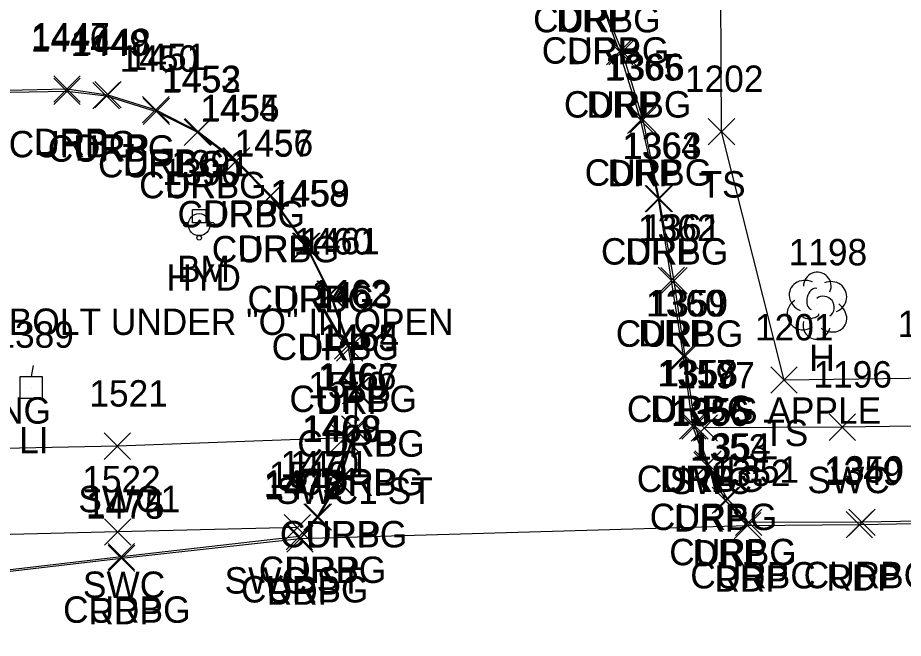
# Model space of a CAD drawing. Extents: x 1715662 to 1717487, y 887396 to 890004.
# Drawn here: x 1716283.7 to 1716350.8, y 888258 to 888305 of the extents above; entities that cross this region are included whole.
import ezdxf

# ---------------------------------------------------------------- set-up
doc = ezdxf.new("R2010")
doc.units = 0
for name, color, linetype in [('C_A', 7, 'Continuous'), ('C_C', 7, 'Continuous'), ('C_I', 7, 'Continuous'), ('CPBM', 7, 'Continuous'), ('L_A', 7, 'Continuous'), ('L_C', 7, 'Continuous'), ('L_I', 7, 'Continuous'), ('L_TIC', 7, 'Continuous'), ('LELB', 7, 'Continuous'), ('LTD', 7, 'Continuous'), ('P_A', 7, 'Continuous'), ('P_I', 7, 'Continuous'), ('P_TIC', 7, 'Continuous'), ('PET', 7, 'Continuous'), ('R_A', 7, 'Continuous'), ('R_I', 7, 'Continuous'), ('R_TIC', 7, 'Continuous'), ('RC', 7, 'Continuous'), ('RDP', 7, 'Continuous'), ('RSW', 7, 'Continuous'), ('S_C', 7, 'Continuous'), ('U_A', 7, 'Continuous'), ('U_I', 7, 'Continuous'), ('ULP', 7, 'Continuous'), ('UWFH', 7, 'Continuous')]:
    doc.layers.add(name, color=color, linetype=linetype)

msp = doc.modelspace()

# ---------------------------------------------------------------- linework, layer by layer
at = {"layer": 'CPBM'}
for p, q in [((1716296.998, 888289.479), (1716296.998, 888290.479)), ((1716296.998, 888290.479), (1716297.998, 888290.479)), ((1716297.5, 888289.979), (1716297.5, 888289.979)), ((1716297.5, 888289.979), (1716297.5, 888289.979)), ((1716297.998, 888290.479), (1716297.998, 888289.479)), ((1716297.998, 888289.479), (1716296.998, 888289.479))]:
    msp.add_line(p, q, dxfattribs=at)
at = {"layer": 'L_TIC'}
for points in [[(1716336.074, 888295.382), (1716338.074, 888297.382)], [(1716338.074, 888295.382), (1716336.074, 888297.382)], [(1716340.818, 888276.563), (1716342.818, 888278.563)], [(1716342.818, 888276.563), (1716340.818, 888278.563)]]:
    msp.add_lwpolyline(points, dxfattribs=at)
at = {"layer": 'LELB'}
msp.add_lwpolyline([(1716373.854, 888277.981), (1716341.818, 888277.563), (1716337.074, 888296.382), (1716336.988, 888312.112), (1716344.519, 888320.79), (1716334.379, 888337.453)], dxfattribs=at)
at = {"layer": 'LTD'}
msp.add_line((1716344.289, 888283.248), (1716344.289, 888283.248), dxfattribs=at)
msp.add_line((1716344.289, 888283.248), (1716344.289, 888283.248), dxfattribs=at)
msp.add_arc((1716344.336, 888284.682), 1.047, 335.52715, 180.95627, dxfattribs=at)
for centre, major_axis, ratio, start_param, end_param in [((1716343.498, 888283.914), (1.21, -0.512), 0.895232, 1.570796, 4.712389), ((1716345.331, 888283.831), (-1.141, -0.483), 0.949671, 1.570796, 4.712389), ((1716344.081, 888283.706), (-0.208, -0.792), 0.645439, 3.141593, 6.283185), ((1716344.789, 888283.081), (-0.5, 0.667), 0.989748, 3.141593, 6.283185), ((1716343.206, 888282.539), (0.584, -1.042), 0.959034, 3.141593, 6.283185), ((1716345.289, 888282.414), (-1.09, 0.792), 0.841452, 1.570796, 4.712389), ((1716344.29, 888281.748), (0.265, 1.061), 0.942809, 1.570796, 4.712389), ((1716343.831, 888282.498), (-0.625, -0.083), 0.423636, 0, 3.141593)]:
    msp.add_ellipse(centre, major_axis=major_axis, ratio=ratio, start_param=start_param, end_param=end_param, dxfattribs=at)
at = {"layer": 'P_TIC'}
for points in [[(1716338.044, 888265.533), (1716340.044, 888267.533)], [(1716340.044, 888265.533), (1716338.044, 888267.533)], [(1716346.525, 888265.611), (1716348.525, 888267.611)], [(1716348.525, 888265.611), (1716346.525, 888267.611)], [(1716304.127, 888264.54), (1716306.127, 888266.54)], [(1716306.127, 888264.54), (1716304.127, 888266.54)], [(1716290.61, 888263.06), (1716292.61, 888265.06)], [(1716292.61, 888263.06), (1716290.61, 888265.06)]]:
    msp.add_lwpolyline(points, dxfattribs=at)
at = {"layer": 'PET'}
msp.add_lwpolyline([(1716527, 888260.728), (1716516.575, 888259.254), (1716502.433, 888259.092), (1716473.824, 888260.93), (1716440.241, 888263.084), (1716411.867, 888267.674), (1716401.494, 888267.443), (1716378.307, 888267.153), (1716347.525, 888266.611), (1716339.044, 888266.533), (1716305.127, 888265.54), (1716291.61, 888264.06), (1716269.77, 888261.49)], dxfattribs=at)
at = {"layer": 'R_TIC'}
for points in [[(1716328.357, 888301.427), (1716330.357, 888303.427)], [(1716330.357, 888301.427), (1716328.357, 888303.427)], [(1716328.548, 888301.44), (1716330.548, 888303.44)], [(1716330.548, 888301.44), (1716328.548, 888303.44)], [(1716286.478, 888298.606), (1716288.478, 888300.606)], [(1716288.478, 888298.606), (1716286.478, 888300.606)], [(1716286.483, 888298.431), (1716288.483, 888300.431)], [(1716288.483, 888298.431), (1716286.483, 888300.431)], [(1716289.447, 888298.096), (1716291.447, 888300.096)], [(1716291.447, 888298.096), (1716289.447, 888300.096)], [(1716289.586, 888298.167), (1716291.586, 888300.167)], [(1716291.586, 888298.167), (1716289.586, 888300.167)], [(1716293.21, 888297.032), (1716295.21, 888299.032)], [(1716295.21, 888297.032), (1716293.21, 888299.032)], [(1716293.246, 888296.912), (1716295.246, 888298.912)], [(1716295.246, 888296.912), (1716293.246, 888298.912)], [(1716329.95, 888296.244), (1716331.95, 888298.244)], [(1716331.95, 888296.244), (1716329.95, 888298.244)], [(1716330.126, 888296.278), (1716332.126, 888298.278)], [(1716332.126, 888296.278), (1716330.126, 888298.278)], [(1716296.419, 888295.376), (1716298.419, 888297.376)], [(1716298.419, 888295.376), (1716296.419, 888297.376)], [(1716296.366, 888295.331), (1716298.366, 888297.331)], [(1716298.366, 888295.331), (1716296.366, 888297.331)], [(1716299.274, 888293.125), (1716301.274, 888295.125)], [(1716301.274, 888293.125), (1716299.274, 888295.125)], [(1716299.338, 888293.175), (1716301.338, 888295.175)], [(1716301.338, 888293.175), (1716299.338, 888295.175)], [(1716301.866, 888290.476), (1716303.866, 888292.476)], [(1716303.866, 888290.476), (1716301.866, 888292.476)], [(1716301.933, 888290.519), (1716303.933, 888292.519)], [(1716303.933, 888290.519), (1716301.933, 888292.519)], [(1716331.288, 888290.299), (1716333.288, 888292.299)], [(1716333.288, 888290.299), (1716331.288, 888292.299)], [(1716331.357, 888290.306), (1716333.357, 888292.306)], [(1716333.357, 888290.306), (1716331.357, 888292.306)], [(1716304.575, 888286.699), (1716306.575, 888288.699)], [(1716306.575, 888286.699), (1716304.575, 888288.699)], [(1716304.656, 888286.714), (1716306.656, 888288.714)], [(1716306.656, 888286.714), (1716304.656, 888288.714)], [(1716332.274, 888284.104), (1716334.274, 888286.104)], [(1716334.274, 888284.104), (1716332.274, 888286.104)], [(1716332.482, 888284.082), (1716334.482, 888286.082)], [(1716334.482, 888284.082), (1716332.482, 888286.082)], [(1716306.406, 888283.086), (1716308.406, 888285.086)], [(1716308.406, 888283.086), (1716306.406, 888285.086)], [(1716306.48, 888283.067), (1716308.48, 888285.067)], [(1716308.48, 888283.067), (1716306.48, 888285.067)], [(1716307.753, 888279.143), (1716309.753, 888281.143)], [(1716309.753, 888279.143), (1716307.753, 888281.143)], [(1716307.904, 888278.993), (1716309.904, 888280.993)], [(1716309.904, 888278.993), (1716307.904, 888280.993)], [(1716333.186, 888278.376), (1716335.186, 888280.376)], [(1716335.186, 888278.376), (1716333.186, 888280.376)], [(1716333.322, 888278.378), (1716335.322, 888280.378)], [(1716335.322, 888278.378), (1716333.322, 888280.378)], [(1716308.35, 888275.756), (1716310.35, 888277.756)], [(1716310.35, 888275.756), (1716308.35, 888277.756)], [(1716308.436, 888275.784), (1716310.436, 888277.784)], [(1716310.436, 888275.784), (1716308.436, 888277.784)], [(1716308.29, 888272.841), (1716310.29, 888274.841)], [(1716310.29, 888272.841), (1716308.29, 888274.841)], [(1716308.376, 888272.785), (1716310.376, 888274.785)], [(1716310.376, 888272.785), (1716308.376, 888274.785)], [(1716333.899, 888273.075), (1716335.899, 888275.075)], [(1716335.899, 888273.075), (1716333.899, 888275.075)], [(1716334.071, 888273.086), (1716336.071, 888275.086)], [(1716336.071, 888273.086), (1716334.071, 888275.086)], [(1716334.781, 888272.932), (1716336.781, 888274.932)], [(1716336.781, 888272.932), (1716334.781, 888274.932)], [(1716345.221, 888272.995), (1716347.221, 888274.995)], [(1716347.221, 888272.995), (1716345.221, 888274.995)], [(1716307.53, 888272.184), (1716309.53, 888274.184)], [(1716309.53, 888272.184), (1716307.53, 888274.184)], [(1716290.3, 888271.553), (1716292.3, 888273.553)], [(1716292.3, 888271.553), (1716290.3, 888273.553)], [(1716334.981, 888270.089), (1716336.981, 888272.089)], [(1716336.981, 888270.089), (1716334.981, 888272.089)], [(1716335.051, 888270.2), (1716337.051, 888272.2)], [(1716337.051, 888270.2), (1716335.051, 888272.2)], [(1716307.028, 888268.889), (1716309.028, 888270.889)], [(1716309.028, 888268.889), (1716307.028, 888270.889)], [(1716307.107, 888268.878), (1716309.107, 888270.878)], [(1716309.107, 888268.878), (1716307.107, 888270.878)], [(1716336.372, 888267.457), (1716338.372, 888269.457)], [(1716338.372, 888267.457), (1716336.372, 888269.457)], [(1716336.533, 888267.537), (1716338.533, 888269.537)], [(1716338.533, 888267.537), (1716336.533, 888269.537)], [(1716336.533, 888267.537), (1716338.533, 888269.537)], [(1716338.533, 888267.537), (1716336.533, 888269.537)], [(1716305.434, 888266.196), (1716307.434, 888268.196)], [(1716307.434, 888266.196), (1716305.434, 888268.196)], [(1716305.525, 888266.198), (1716307.525, 888268.198)], [(1716307.525, 888266.198), (1716305.525, 888268.198)], [(1716303.924, 888265.392), (1716305.924, 888267.392)], [(1716305.924, 888265.392), (1716303.924, 888267.392)], [(1716338.044, 888265.533), (1716340.044, 888267.533)], [(1716340.044, 888265.533), (1716338.044, 888267.533)], [(1716338.127, 888265.78), (1716340.127, 888267.78)], [(1716340.127, 888265.78), (1716338.127, 888267.78)], [(1716346.715, 888265.797), (1716348.715, 888267.797)], [(1716348.715, 888265.797), (1716346.715, 888267.797)], [(1716290.325, 888265.062), (1716292.325, 888267.062)], [(1716292.325, 888265.062), (1716290.325, 888267.062)], [(1716304.079, 888264.717), (1716306.079, 888266.717)], [(1716306.079, 888264.717), (1716304.079, 888266.717)], [(1716304.127, 888264.54), (1716306.127, 888266.54)], [(1716306.127, 888264.54), (1716304.127, 888266.54)], [(1716290.602, 888263.18), (1716292.602, 888265.18)], [(1716292.602, 888263.18), (1716290.602, 888265.18)]]:
    msp.add_lwpolyline(points, dxfattribs=at)
at = {"layer": 'RC'}
for points in [[(1716337.533, 888268.537), (1716336.051, 888271.2), (1716335.071, 888274.086), (1716334.322, 888279.378), (1716333.482, 888285.082), (1716332.357, 888291.306), (1716331.126, 888297.278), (1716329.548, 888302.44), (1716327.871, 888306.522), (1716327.215, 888308.893), (1716327.82, 888311.356), (1716329.578, 888313.455), (1716339.139, 888321.4), (1716332.656, 888333.374)], [(1716261.527, 888298.996), (1716287.483, 888299.431), (1716290.447, 888299.096), (1716294.246, 888297.912), (1716297.366, 888296.331), (1716300.274, 888294.125), (1716302.866, 888291.476), (1716305.575, 888287.699), (1716307.406, 888284.086), (1716308.753, 888280.143), (1716309.35, 888276.756), (1716309.29, 888273.841), (1716308.028, 888269.889), (1716306.434, 888267.196), (1716305.079, 888265.717), (1716291.602, 888264.18), (1716269.776, 888261.634)], [(1716401.116, 888268.058), (1716378.574, 888267.336), (1716347.715, 888266.797), (1716339.127, 888266.78), (1716337.533, 888268.537)]]:
    msp.add_lwpolyline(points, dxfattribs=at)
at = {"layer": 'RDP'}
for points in [[(1716339.044, 888266.533), (1716337.372, 888268.457), (1716335.981, 888271.089), (1716334.899, 888274.075), (1716334.186, 888279.376), (1716333.274, 888285.104), (1716332.288, 888291.299), (1716330.95, 888297.244), (1716329.357, 888302.427), (1716327.85, 888306.482), (1716327.06, 888308.938), (1716327.66, 888311.412), (1716329.475, 888313.512), (1716339.024, 888321.455), (1716332.507, 888333.43)], [(1716189.024, 888300.786), (1716195.154, 888295.541), (1716202.194, 888288.263), (1716208.512, 888281.139), (1716229.206, 888296.357), (1716232.872, 888297.892), (1716235.84, 888298.504), (1716261.496, 888299.043), (1716287.478, 888299.606), (1716290.586, 888299.167), (1716294.21, 888298.032), (1716297.419, 888296.376), (1716300.338, 888294.175), (1716302.933, 888291.519), (1716305.656, 888287.714), (1716307.48, 888284.067), (1716308.904, 888279.993), (1716309.436, 888276.784), (1716309.376, 888273.785), (1716308.107, 888269.878), (1716306.525, 888267.198), (1716305.127, 888265.54)]]:
    msp.add_lwpolyline(points, dxfattribs=at)
at = {"layer": 'RSW'}
for points in [[(1716401.494, 888267.443), (1716400.217, 888275.488), (1716393.811, 888275.383), (1716384.363, 888275.19), (1716362.415, 888274.225), (1716346.221, 888273.995), (1716335.781, 888273.932)], [(1716308.53, 888273.184), (1716291.3, 888272.553), (1716259.154, 888271.89), (1716226.643, 888270.982), (1716193.784, 888269.889), (1716164.394, 888265.223), (1716160.716, 888264.617), (1716155.847, 888262.476), (1716141.722, 888256.045), (1716137.135, 888254.024), (1716108.704, 888240.881), (1716099.258, 888236.591), (1716079.333, 888227.087)], [(1716304.924, 888266.392), (1716291.325, 888266.062), (1716259.803, 888265.285), (1716226.621, 888264.409), (1716194.985, 888263.34), (1716161.734, 888257.864), (1716139.704, 888247.707), (1716119.85, 888238.533), (1716083.389, 888221.288)]]:
    msp.add_lwpolyline(points, dxfattribs=at)
at = {"layer": 'ULP'}
for p, q in [((1716284.921, 888278.675), (1716284.755, 888277.841)), ((1716283.921, 888276.175), (1716283.921, 888277.841)), ((1716283.921, 888277.841), (1716285.588, 888277.841)), ((1716285.588, 888277.841), (1716285.588, 888276.175)), ((1716284.755, 888277.008), (1716284.755, 888277.008)), ((1716285.588, 888276.175), (1716283.921, 888276.175)), ((1716284.505, 888275.342), (1716284.755, 888276.175))]:
    msp.add_line(p, q, dxfattribs=at)
at = {"layer": 'UWFH'}
msp.add_line((1716297.494, 888289.332), (1716297.494, 888289.332), dxfattribs=at)
for centre, radius in [((1716297.494, 888289.332), 0.833), ((1716296.494, 888289.332), 0.167), ((1716298.494, 888289.332), 0.167), ((1716297.494, 888288.332), 0.167)]:
    msp.add_circle(centre, radius, dxfattribs=at)

# ---------------------------------------------------------------- texts
at = {"layer": 'C_A'}
msp.add_text('BM', height=2, dxfattribs=at).set_placement((1716295.815, 888284.979))
at = {"layer": 'C_C'}
msp.add_text('TOP OF BOLT UNDER "O" IN OPEN', height=2, dxfattribs=at).set_placement((1716272.374, 888280.979))
at = {"layer": 'C_I'}
msp.add_text('1391', height=2, dxfattribs=at).set_placement((1716295.374, 888292.979))
at = {"layer": 'L_A'}
for s, p in [('TS', (1716335.483, 888291.382)), ('H', (1716343.722, 888278.248)), ('TS', (1716340.227, 888272.563))]:
    msp.add_text(s, height=2, dxfattribs=at).set_placement(p)
at = {"layer": 'L_C'}
msp.add_text('S APPLE', height=2, dxfattribs=at).set_placement((1716338.022, 888274.248))
at = {"layer": 'L_I'}
for s, p in [('1202', (1716334.302, 888299.382)), ('1198', (1716342.163, 888286.248)), ('1201', (1716339.613, 888280.563))]:
    msp.add_text(s, height=2, dxfattribs=at).set_placement(p)
at = {"layer": 'P_A'}
for p in [(1716336.533, 888261.533), (1716345.013, 888261.611), (1716302.615, 888260.54), (1716289.098, 888259.06)]:
    msp.add_text('RDP', height=2, dxfattribs=at).set_placement(p)
at = {"layer": 'P_I'}
for s, p in [('1352', (1716336.352, 888269.533)), ('1349', (1716344.824, 888269.611)), ('1472', (1716302.434, 888268.54)), ('1475', (1716288.917, 888267.06))]:
    msp.add_text(s, height=2, dxfattribs=at).set_placement(p)
at = {"layer": 'R_A'}
for s, p in [('CURBG', (1716322.798, 888303.893)), ('DRP', (1716324.548, 888303.938)), ('CURBG', (1716323.453, 888301.522)), ('DRP', (1716325.338, 888301.482)), ('CURBG', (1716325.131, 888297.44)), ('DRP', (1716326.845, 888297.427)), ('CURBG', (1716283.066, 888294.431)), ('DRP', (1716284.966, 888294.606)), ('CURBG', (1716286.03, 888294.096)), ('DRP', (1716288.074, 888294.167)), ('CURBG', (1716289.829, 888292.912)), ('DRP', (1716291.698, 888293.032)), ('CURBG', (1716326.708, 888292.278)), ('DRP', (1716328.439, 888292.244)), ('CURBG', (1716292.948, 888291.331)), ('DRP', (1716294.907, 888291.376)), ('CURBG', (1716295.856, 888289.125)), ('DRP', (1716297.826, 888289.175)), ('CURBG', (1716298.449, 888286.476)), ('DRP', (1716300.421, 888286.519)), ('CURBG', (1716327.94, 888286.306)), ('DRP', (1716329.776, 888286.299)), ('CURBG', (1716301.157, 888282.699)), ('DRP', (1716303.144, 888282.714)), ('CURBG', (1716329.065, 888280.082)), ('DRP', (1716330.762, 888280.104)), ('CURBG', (1716302.989, 888279.086)), ('DRP', (1716304.968, 888279.067)), ('CURBG', (1716304.336, 888275.143)), ('DRP', (1716306.393, 888274.993)), ('CURBG', (1716329.905, 888274.378)), ('DRP', (1716331.674, 888274.376)), ('CURBG', (1716304.932, 888271.756)), ('DRP', (1716306.924, 888271.784)), ('CURBG', (1716304.872, 888268.841)), ('DRP', (1716306.864, 888268.785)), ('CURBG', (1716330.654, 888269.086)), ('DRP', (1716332.388, 888269.075)), ('SWC', (1716333.144, 888268.932)), ('SWC', (1716343.583, 888268.995)), ('SWC1 ST', (1716303.31, 888268.184)), ('SWC1', (1716288.34, 888267.553)), ('CURBG', (1716331.634, 888266.2)), ('DRP', (1716333.469, 888266.089)), ('CURBG', (1716303.61, 888264.889)), ('DRP', (1716305.595, 888264.878)), ('CURBC', (1716333.116, 888263.537)), ('CURBG', (1716333.116, 888263.537)), ('DRP', (1716334.86, 888263.457)), ('CURBG', (1716302.016, 888262.196)), ('DRP', (1716304.014, 888262.198)), ('CURBC', (1716334.71, 888261.78)), ('CURBC', (1716343.298, 888261.797)), ('SWC ST', (1716299.42, 888261.392)), ('DRP', (1716336.533, 888261.533)), ('SWC', (1716288.687, 888261.062)), ('CURBG', (1716300.662, 888260.717)), ('DRP', (1716302.615, 888260.54)), ('CURBG', (1716287.184, 888259.18))]:
    msp.add_text(s, height=2, dxfattribs=at).set_placement(p)
at = {"layer": 'R_I'}
for s, p in [('1446', (1716284.735, 888302.431)), ('1447', (1716284.785, 888302.606)), ('1449', (1716287.746, 888302.096)), ('1448', (1716287.893, 888302.167)), ('1450', (1716291.467, 888300.912)), ('1451', (1716292.084, 888301.032)), ('1365', (1716328.21, 888300.244)), ('1366', (1716328.33, 888300.278)), ('1452', (1716294.726, 888299.376)), ('1453', (1716294.673, 888299.331)), ('1454', (1716297.581, 888297.125)), ('1455', (1716297.645, 888297.175)), ('1457', (1716300.173, 888294.476)), ('1456', (1716300.185, 888294.519)), ('1364', (1716329.548, 888294.299)), ('1363', (1716329.617, 888294.306)), ('1458', (1716302.882, 888290.699)), ('1459', (1716302.955, 888290.714)), ('1362', (1716330.742, 888288.082)), ('1361', (1716331.1, 888288.104)), ('1460', (1716304.653, 888287.067)), ('1461', (1716305.233, 888287.086)), ('1462', (1716306.013, 888283.143)), ('1463', (1716306.164, 888282.993)), ('1360', (1716331.359, 888282.376)), ('1359', (1716331.622, 888282.378)), ('1465', (1716306.609, 888279.756)), ('1464', (1716306.695, 888279.784)), ('1466', (1716306.494, 888276.841)), ('1467', (1716306.635, 888276.785)), ('1357', (1716332.207, 888277.075)), ('1358', (1716332.378, 888277.086)), ('1197', (1716333.655, 888276.932)), ('1196', (1716344.04, 888276.995)), ('1520', (1716305.751, 888276.184)), ('1521', (1716289.174, 888275.553)), ('1356', (1716333.233, 888274.089)), ('1355', (1716333.359, 888274.2)), ('1469', (1716305.28, 888272.889)), ('1468', (1716305.367, 888272.878)), ('1353', (1716334.679, 888271.457)), ('1354', (1716334.84, 888271.537)), ('1354', (1716334.84, 888271.537)), ('1470', (1716303.654, 888270.196)), ('1471', (1716304.399, 888270.198)), ('1519', (1716302.79, 888269.392)), ('1352', (1716336.352, 888269.533)), ('1351', (1716337.001, 888269.78)), ('1350', (1716344.936, 888269.797)), ('1522', (1716288.632, 888269.062)), ('1473', (1716302.387, 888268.717)), ('1472', (1716302.434, 888268.54)), ('1474', (1716288.909, 888267.18))]:
    msp.add_text(s, height=2, dxfattribs=at).set_placement(p)
at = {"layer": 'S_C'}
msp.add_text('WARREN "JERSEY" DROWN PARKING', height=2, dxfattribs=at).set_placement((1716237.413, 888274.262))
at = {"layer": 'U_A'}
for s, p in [('HYD', (1716295.014, 888284.332)), ('LI', (1716283.857, 888272.008))]:
    msp.add_text(s, height=2, dxfattribs=at).set_placement(p)
at = {"layer": 'U_I'}
for s, p in [('1390', (1716294.715, 888292.332)), ('1199', (1716350.426, 888280.82)), ('1389', (1716282.054, 888280.008))]:
    msp.add_text(s, height=2, dxfattribs=at).set_placement(p)

doc.saveas('drawing.dxf')
